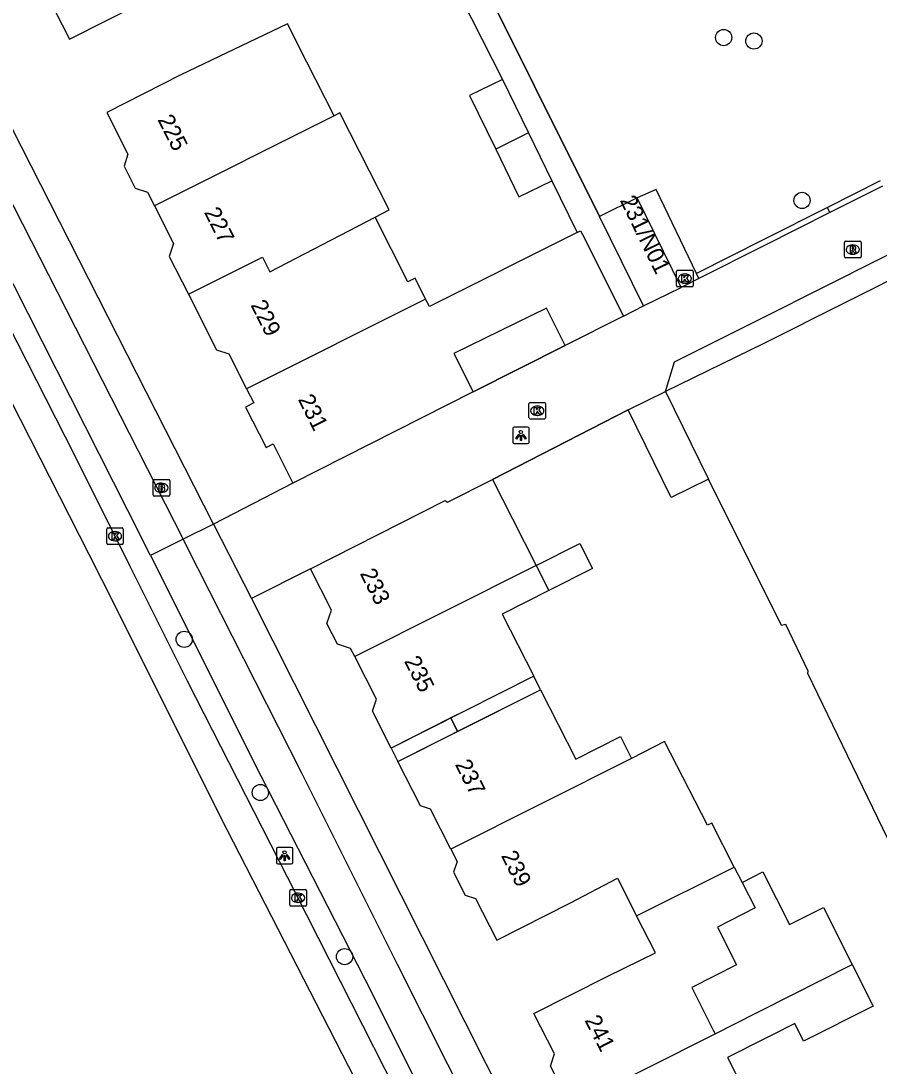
# Model space of a CAD drawing. Extents: x 162347 to 162868, y 381221 to 381813.
# Drawn here: x 162455.2 to 162507, y 381421.7 to 381484.8 of the extents above; entities that cross this region are included whole.
import ezdxf

# ---------------------------------------------------------------- set-up
doc = ezdxf.new("R2010")
doc.units = 0
for name, color, linetype in [('IMGEO_Boom', 7, 'Continuous'), ('IMGEO_Brandkraan', 7, 'Continuous'), ('IMGEO_Fietspad_open', 7, 'Continuous'), ('IMGEO_Groenvoorziening', 7, 'Continuous'), ('IMGEO_Hek', 7, 'Continuous'), ('IMGEO_Kolk', 7, 'Continuous'), ('IMGEO_Lichtpunt', 7, 'Continuous'), ('IMGEO_Muur', 7, 'Continuous'), ('IMGEO_Pand', 7, 'Continuous'), ('IMGEO_Pand_nummerreeks', 7, 'Continuous'), ('IMGEO_Pand_overbouw', 7, 'Continuous'), ('IMGEO_Parkeervlak_open', 7, 'Continuous'), ('IMGEO_Rijbaan_regionaal_gesloten', 7, 'Continuous'), ('IMGEO_Rioolput', 7, 'Continuous'), ('IMGEO_Voetpad_open', 7, 'Continuous')]:
    doc.layers.add(name, color=color, linetype=linetype)

msp = doc.modelspace()

# ---------------------------------------------------------------- linework, layer by layer
at = {"layer": 'IMGEO_Boom'}
for centre in [(162497.584, 381483.799), (162499.409, 381483.589), (162502.314, 381473.971), (162465.021, 381447.483), (162469.618, 381438.236), (162474.702, 381428.333)]:
    msp.add_circle(centre, 0.489, dxfattribs=at)
at = {"layer": 'IMGEO_Brandkraan'}
for p, q in [((162463.144, 381456.2), (162463.144, 381457.052)), ((162463.219, 381457.126), (162464.071, 381457.126)), ((162463.632, 381456.906), (162463.657, 381456.906)), ((162464.145, 381457.052), (162464.145, 381456.2)), ((162464.071, 381456.126), (162463.219, 381456.126)), ((162463.655, 381456.346), (162463.63, 381456.346))]:
    msp.add_line(p, q, dxfattribs=at)
for points in [[(162463.144, 381456.2), (162463.144, 381457.052)], [(162463.219, 381457.126), (162464.071, 381457.126)], [(162463.492, 381456.826), (162463.492, 381456.426), (162463.705, 381456.426)], [(162463.723, 381456.826), (162463.492, 381456.826)], [(162463.671, 381456.745), (162463.617, 381456.745), (162463.617, 381456.669)], [(162463.617, 381456.669), (162463.67, 381456.669)], [(162463.679, 381456.593), (162463.617, 381456.593), (162463.617, 381456.512)], [(162464.145, 381457.052), (162464.145, 381456.2)], [(162464.071, 381456.126), (162463.219, 381456.126)], [(162463.617, 381456.512), (162463.679, 381456.512)]]:
    msp.add_lwpolyline(points, dxfattribs=at)
for centre, radius, start, end in [((162463.221, 381457.05), 0.0765, 91.55205, 178.44795), ((162463.221, 381457.05), 0.0765, 91.55205, 178.44795), ((162463.672, 381456.707), 0.0379, 267.82845, 90.93552), ((162463.68, 381456.552), 0.0404, 269.87594, 90.50774), ((162463.727, 381456.681), 0.145, 59.4692, 91.53667), ((162463.752, 381456.728), 0.0922, 285.51372, 58.15012), ((162463.757, 381456.536), 0.105, 301.31148, 78.98903), ((162464.069, 381457.05), 0.0765, 1.55205, 88.44795), ((162464.069, 381457.05), 0.0765, 1.55205, 88.44795), ((162463.221, 381456.202), 0.0765, 181.55205, 268.44795), ((162463.221, 381456.202), 0.0765, 181.55205, 268.44795), ((162463.711, 381456.677), 0.251, 268.66757, 293.53466), ((162464.069, 381456.202), 0.0765, 271.55205, 358.44795), ((162464.069, 381456.202), 0.0765, 271.55205, 358.44795)]:
    msp.add_arc(centre, radius, start, end, dxfattribs=at)
for centre, major_axis, ratio, start_param, end_param in [((162463.631, 381456.626), (-0.387, 0.002), 0.722429, 4.712389, 7.853982), ((162463.656, 381456.626), (-0.39, 0.002), 0.717154, 1.570796, 4.712389)]:
    msp.add_ellipse(centre, major_axis=major_axis, ratio=ratio, start_param=start_param, end_param=end_param, dxfattribs=at)
at = {"layer": 'IMGEO_Fietspad_open'}
for points in [[(162362.948, 381654.184), (162366.42, 381647.346), (162373.547, 381633.19), (162382.229, 381616.136), (162390.519, 381599.747), (162395.607, 381589.625), (162403.109, 381574.937), (162411.637, 381558.14), (162419.849, 381541.928), (162427.81, 381526.456), (162437.491, 381507.399), (162441.265, 381500), (162456.812, 381469.521), (162464.953, 381453.521)], [(162462.98, 381452.545), (162461.625, 381455.252), (162453.003, 381472.242), (162452.042, 381474.115), (162448.969, 381480.106), (162445.183, 381487.485), (162438.839, 381500), (162438.556, 381500.561), (162435.485, 381506.617), (162424.679, 381527.923), (162421.176, 381534.828)], [(162464.953, 381453.521), (162462.98, 381452.545)], [(162464.953, 381453.521), (162465.14, 381453.154), (162472.078, 381439.472), (162477.869, 381427.872), (162483.955, 381415.809), (162489.755, 381404.169), (162492.348, 381399.133), (162497.104, 381389.763), (162499.049, 381385.783), (162500, 381383.793), (162500.427, 381382.899)], [(162462.98, 381452.545), (162469.637, 381439.248), (162476.371, 381426.111), (162479.042, 381420.737), (162481.428, 381415.937), (162487.993, 381402.969), (162489.759, 381399.475), (162492.407, 381394.237), (162495.213, 381388.634), (162496.259, 381386.553), (162497.483, 381384.161), (162498.087, 381382.794), (162500, 381378.338), (162501.86, 381374.016), (162502.544, 381372.608), (162503.198, 381371.132), (162503.882, 381369.785), (162504.669, 381367.657), (162505.515, 381365.488), (162506.466, 381362.909), (162506.901, 381361.574)]]:
    msp.add_lwpolyline(points, dxfattribs=at)
at = {"layer": 'IMGEO_Groenvoorziening'}
for points in [[(162560.659, 381495.777), (162538.071, 381484.442), (162500, 381465.338), (162494.068, 381462.441)], [(162507.027, 381475.147), (162503.84, 381473.541)], [(162503.84, 381473.541), (162500, 381471.606), (162495.941, 381469.56)], [(162503.991, 381473.241), (162503.84, 381473.541)], [(162512.923, 381424.22), (162502.662, 381445.418), (162502.674, 381445.558), (162501.325, 381448.372), (162501.075, 381448.315), (162496.664, 381457.154)]]:
    msp.add_lwpolyline(points, dxfattribs=at)
at = {"layer": 'IMGEO_Hek'}
msp.add_lwpolyline([(162474.241, 381507.266), (162474.364, 381504.517), (162490.097, 381473.002)], dxfattribs=at)
at = {"layer": 'IMGEO_Kolk'}
for p, q in [((162494.739, 381468.827), (162494.739, 381469.679)), ((162494.814, 381469.753), (162495.666, 381469.753)), ((162495.227, 381469.533), (162495.252, 381469.533)), ((162495.74, 381469.679), (162495.74, 381468.827)), ((162495.666, 381468.753), (162494.814, 381468.753)), ((162495.25, 381468.973), (162495.225, 381468.973)), ((162485.832, 381460.853), (162485.832, 381461.705)), ((162485.907, 381461.779), (162486.759, 381461.779)), ((162486.833, 381461.705), (162486.833, 381460.853)), ((162486.343, 381460.999), (162486.318, 381460.999)), ((162486.32, 381461.559), (162486.345, 381461.559)), ((162486.759, 381460.779), (162485.907, 381460.779)), ((162460.342, 381453.28), (162460.342, 381454.132)), ((162460.417, 381454.206), (162461.269, 381454.206)), ((162461.343, 381454.132), (162461.343, 381453.28)), ((162460.83, 381453.986), (162460.855, 381453.986)), ((162461.269, 381453.206), (162460.417, 381453.206)), ((162460.853, 381453.426), (162460.828, 381453.426)), ((162471.394, 381431.456), (162471.394, 381432.308)), ((162471.469, 381432.382), (162472.321, 381432.382)), ((162471.882, 381432.162), (162471.907, 381432.162)), ((162472.395, 381432.308), (162472.395, 381431.456)), ((162472.321, 381431.382), (162471.469, 381431.382)), ((162471.905, 381431.602), (162471.88, 381431.602))]:
    msp.add_line(p, q, dxfattribs=at)
for points in [[(162494.739, 381468.827), (162494.739, 381469.679)], [(162494.814, 381469.753), (162495.666, 381469.753)], [(162495.06, 381469.453), (162495.183, 381469.453), (162495.183, 381469.302), (162495.313, 381469.453), (162495.477, 381469.453), (162495.331, 381469.302), (162495.484, 381469.053), (162495.332, 381469.053), (162495.247, 381469.217), (162495.183, 381469.15), (162495.183, 381469.053), (162495.06, 381469.053), (162495.06, 381469.453)], [(162495.74, 381469.679), (162495.74, 381468.827)], [(162495.666, 381468.753), (162494.814, 381468.753)], [(162485.832, 381460.853), (162485.832, 381461.705)], [(162485.907, 381461.779), (162486.759, 381461.779)], [(162486.833, 381461.705), (162486.833, 381460.853)], [(162486.153, 381461.479), (162486.276, 381461.479), (162486.276, 381461.328), (162486.406, 381461.479), (162486.57, 381461.479), (162486.424, 381461.328), (162486.577, 381461.079), (162486.425, 381461.079), (162486.34, 381461.243), (162486.276, 381461.176), (162486.276, 381461.079), (162486.153, 381461.079), (162486.153, 381461.479)], [(162486.759, 381460.779), (162485.907, 381460.779)], [(162460.342, 381453.28), (162460.342, 381454.132)], [(162460.417, 381454.206), (162461.269, 381454.206)], [(162461.343, 381454.132), (162461.343, 381453.28)], [(162460.663, 381453.906), (162460.786, 381453.906), (162460.786, 381453.755), (162460.916, 381453.906), (162461.08, 381453.906), (162460.934, 381453.755), (162461.087, 381453.506), (162460.935, 381453.506), (162460.85, 381453.67), (162460.786, 381453.603), (162460.786, 381453.506), (162460.663, 381453.506), (162460.663, 381453.906)], [(162461.269, 381453.206), (162460.417, 381453.206)], [(162471.394, 381431.456), (162471.394, 381432.308)], [(162471.469, 381432.382), (162472.321, 381432.382)], [(162471.715, 381432.082), (162471.838, 381432.082), (162471.838, 381431.931), (162471.968, 381432.082), (162472.132, 381432.082), (162471.986, 381431.931), (162472.139, 381431.682), (162471.987, 381431.682), (162471.902, 381431.846), (162471.838, 381431.779), (162471.838, 381431.682), (162471.715, 381431.682), (162471.715, 381432.082)], [(162472.395, 381432.308), (162472.395, 381431.456)], [(162472.321, 381431.382), (162471.469, 381431.382)]]:
    msp.add_lwpolyline(points, dxfattribs=at)
for centre, start, end in [((162494.816, 381469.677), 91.55205, 178.44795), ((162494.816, 381469.677), 91.55205, 178.44795), ((162495.664, 381469.677), 1.55205, 88.44795), ((162495.664, 381469.677), 1.55205, 88.44795), ((162494.816, 381468.829), 181.55205, 268.44795), ((162494.816, 381468.829), 181.55205, 268.44795), ((162495.664, 381468.829), 271.55205, 358.44795), ((162495.664, 381468.829), 271.55205, 358.44795), ((162485.909, 381461.703), 91.55205, 178.44795), ((162485.909, 381461.703), 91.55205, 178.44795), ((162486.757, 381461.703), 1.55205, 88.44795), ((162486.757, 381461.703), 1.55205, 88.44795), ((162485.909, 381460.855), 181.55205, 268.44795), ((162485.909, 381460.855), 181.55205, 268.44795), ((162486.757, 381460.855), 271.55205, 358.44795), ((162486.757, 381460.855), 271.55205, 358.44795), ((162460.419, 381454.13), 91.55205, 178.44795), ((162460.419, 381454.13), 91.55205, 178.44795), ((162461.267, 381454.13), 1.55205, 88.44795), ((162461.267, 381454.13), 1.55205, 88.44795), ((162460.419, 381453.282), 181.55205, 268.44795), ((162460.419, 381453.282), 181.55205, 268.44795), ((162461.267, 381453.282), 271.55205, 358.44795), ((162461.267, 381453.282), 271.55205, 358.44795), ((162471.471, 381432.306), 91.55205, 178.44795), ((162471.471, 381432.306), 91.55205, 178.44795), ((162472.319, 381432.306), 1.55205, 88.44795), ((162472.319, 381432.306), 1.55205, 88.44795), ((162471.471, 381431.458), 181.55205, 268.44795), ((162471.471, 381431.458), 181.55205, 268.44795), ((162472.319, 381431.458), 271.55205, 358.44795), ((162472.319, 381431.458), 271.55205, 358.44795)]:
    msp.add_arc(centre, 0.0765, start, end, dxfattribs=at)
for centre, major_axis, ratio, start_param, end_param in [((162495.226, 381469.253), (-0.387, 0.002), 0.722429, 4.712389, 7.853982), ((162495.251, 381469.253), (-0.39, 0.002), 0.717154, 1.570796, 4.712389), ((162486.319, 381461.279), (-0.387, 0.002), 0.722429, 4.712389, 7.853982), ((162486.344, 381461.279), (-0.39, 0.002), 0.717154, 1.570796, 4.712389), ((162460.829, 381453.706), (-0.387, 0.002), 0.722429, 4.712389, 7.853982), ((162460.854, 381453.706), (-0.39, 0.002), 0.717154, 1.570796, 4.712389), ((162471.881, 381431.882), (-0.387, 0.002), 0.722429, 4.712389, 7.853982), ((162471.906, 381431.882), (-0.39, 0.002), 0.717154, 1.570796, 4.712389)]:
    msp.add_ellipse(centre, major_axis=major_axis, ratio=ratio, start_param=start_param, end_param=end_param, dxfattribs=at)
at = {"layer": 'IMGEO_Lichtpunt'}
for p, q in [((162484.847, 381460.197), (162484.847, 381459.39)), ((162484.847, 381460.197), (162484.847, 381459.39)), ((162485.749, 381460.292), (162484.941, 381460.292)), ((162485.749, 381460.292), (162484.941, 381460.292)), ((162485.843, 381459.39), (162485.843, 381460.197)), ((162485.843, 381459.39), (162485.843, 381460.197)), ((162484.941, 381459.296), (162485.749, 381459.296)), ((162484.941, 381459.296), (162485.749, 381459.296)), ((162470.582, 381434.829), (162470.582, 381434.022)), ((162470.582, 381434.829), (162470.582, 381434.022)), ((162471.484, 381434.924), (162470.676, 381434.924)), ((162471.484, 381434.924), (162470.676, 381434.924)), ((162471.578, 381434.022), (162471.578, 381434.829)), ((162471.578, 381434.022), (162471.578, 381434.829)), ((162470.676, 381433.928), (162471.484, 381433.928)), ((162470.676, 381433.928), (162471.484, 381433.928))]:
    msp.add_line(p, q, dxfattribs=at)
for points in [[(162485.221, 381459.861), (162485.26, 381459.833), (162485.072, 381459.571), (162485.034, 381459.598), (162485.221, 381459.861)], [(162485.323, 381459.813), (162485.37, 381459.813), (162485.37, 381459.491), (162485.323, 381459.491), (162485.323, 381459.813)], [(162485.433, 381459.833), (162485.471, 381459.86), (162485.658, 381459.598), (162485.619, 381459.57), (162485.433, 381459.833)], [(162470.956, 381434.493), (162470.995, 381434.465), (162470.807, 381434.203), (162470.769, 381434.23), (162470.956, 381434.493)], [(162471.058, 381434.445), (162471.105, 381434.445), (162471.105, 381434.123), (162471.058, 381434.123), (162471.058, 381434.445)], [(162471.168, 381434.465), (162471.206, 381434.492), (162471.393, 381434.23), (162471.354, 381434.202), (162471.168, 381434.465)]]:
    msp.add_lwpolyline(points, dxfattribs=at)
for centre in [(162485.346, 381459.995), (162471.081, 381434.627)]:
    msp.add_circle(centre, 0.0994, dxfattribs=at)
for centre, start, end in [((162484.941, 381460.197), 90, 180), ((162484.941, 381460.197), 90, 180), ((162485.749, 381460.197), 0, 90), ((162485.749, 381460.197), 0, 90), ((162484.941, 381459.39), 180, 270), ((162484.941, 381459.39), 180, 270), ((162485.749, 381459.39), 270, 0), ((162485.749, 381459.39), 270, 360), ((162470.676, 381434.829), 90, 180), ((162470.676, 381434.829), 90, 180), ((162471.484, 381434.829), 0, 90), ((162471.484, 381434.829), 0, 90), ((162470.676, 381434.022), 180, 270), ((162470.676, 381434.022), 180, 270), ((162471.484, 381434.022), 270, 0), ((162471.484, 381434.022), 270, 360)]:
    msp.add_arc(centre, 0.0946, start, end, dxfattribs=at)
at = {"layer": 'IMGEO_Muur'}
for points in [[(162482.458, 381462.415), (162488.025, 381465.214)], [(162483.626, 381457.134), (162491.815, 381461.335)]]:
    msp.add_lwpolyline(points, dxfattribs=at)
at = {"layer": 'IMGEO_Pand'}
for points in [[(162455.242, 381489.376), (162455.676, 381488.518), (162455.426, 381487.753), (162456.046, 381486.527), (162456.789, 381486.284), (162458.093, 381483.707), (162462.554, 381485.966), (162466.136, 381487.779), (162466.036, 381487.977), (162468.845, 381489.399), (162467.607, 381491.843), (162466.077, 381494.864)], [(162474.066, 381479.08), (162472.431, 381482.309), (162471.258, 381484.626), (162464.815, 381481.546), (162460.354, 381479.287), (162461.627, 381476.772), (162461.387, 381476.041), (162462.063, 381474.706), (162462.809, 381474.462), (162463.225, 381473.639)], [(162484.24, 381481.274), (162482.244, 381480.303), (162483.822, 381477.059)], [(162484.24, 381481.274), (162485.806, 381478.056)], [(162474.066, 381479.08), (162463.225, 381473.639)], [(162476.538, 381472.961), (162477.393, 381473.394), (162474.423, 381479.261), (162474.066, 381479.08)], [(162485.806, 381478.056), (162483.822, 381477.059)], [(162485.806, 381478.056), (162487.218, 381475.153)], [(162483.822, 381477.059), (162485.222, 381474.182), (162487.218, 381475.153)], [(162463.225, 381473.639), (162464.375, 381471.367), (162464.119, 381470.585), (162465.272, 381468.307)], [(162492.37, 381474.118), (162490.097, 381473.002)], [(162495.02, 381468.72), (162492.37, 381474.118)], [(162492.747, 381467.604), (162490.097, 381473.002)], [(162465.272, 381468.307), (162469.74, 381470.549), (162470.19, 381469.657), (162476.538, 381472.961)], [(162479.591, 381468.015), (162478.952, 381469.277), (162478.516, 381469.056), (162476.538, 381472.961)], [(162488.733, 381472.039), (162479.821, 381467.56), (162479.591, 381468.015)], [(162488.733, 381472.039), (162488.94, 381472.143), (162489.057, 381471.911), (162491.536, 381466.979)], [(162492.747, 381467.604), (162495.02, 381468.72)], [(162465.272, 381468.307), (162466.973, 381464.949), (162467.715, 381464.705), (162468.785, 381462.592)], [(162479.591, 381468.015), (162468.785, 381462.592)], [(162488.025, 381465.214), (162486.889, 381467.475), (162481.288, 381464.726), (162482.458, 381462.415)], [(162491.536, 381466.979), (162488.025, 381465.214)], [(162468.785, 381462.592), (162469.214, 381461.745), (162468.728, 381461.499), (162469.959, 381459.066), (162470.385, 381459.282), (162471.586, 381456.911)], [(162482.458, 381462.415), (162471.586, 381456.911)], [(162491.815, 381461.335), (162494.068, 381462.441)], [(162494.068, 381462.441), (162496.664, 381457.154)], [(162496.664, 381457.154), (162494.411, 381456.048), (162491.815, 381461.335)], [(162472.642, 381451.739), (162480.771, 381455.855), (162480.915, 381455.761), (162483.626, 381457.134)], [(162483.626, 381457.134), (162484.835, 381454.745), (162486.257, 381451.935)], [(162486.257, 381451.935), (162488.907, 381453.263), (162489.667, 381451.747), (162487.023, 381450.422)], [(162475.313, 381446.45), (162475.068, 381446.933), (162474.268, 381447.195), (162473.637, 381448.441), (162473.902, 381449.25), (162472.642, 381451.739)], [(162486.257, 381451.935), (162475.313, 381446.45)], [(162486.257, 381451.935), (162487.023, 381450.422)], [(162487.023, 381450.422), (162484.222, 381449.004), (162486.116, 381445.261), (162481.973, 381443.172), (162477.508, 381440.921), (162476.386, 381443.138), (162476.623, 381443.862), (162475.313, 381446.45)], [(162481.115, 381434.818), (162479.896, 381437.224), (162479.278, 381437.427), (162477.921, 381440.106), (162482.389, 381442.352), (162486.535, 381444.436), (162488.651, 381440.256), (162491.346, 381441.62), (162492.028, 381440.288)], [(162498.218, 381433.738), (162496.86, 381436.388), (162496.605, 381436.257), (162494.017, 381441.307), (162492.028, 381440.288)], [(162492.028, 381440.288), (162481.115, 381434.818)], [(162481.115, 381434.818), (162481.489, 381434.079), (162481.276, 381433.431), (162481.977, 381432.048), (162482.601, 381431.843), (162483.881, 381429.316), (162488.342, 381431.575), (162491.168, 381433.077), (162492.321, 381430.8)], [(162492.321, 381430.8), (162498.218, 381433.738)], [(162498.218, 381433.738), (162498.693, 381432.81)], [(162498.693, 381432.81), (162499.955, 381433.446), (162501.554, 381430.273), (162503.602, 381431.305), (162505.342, 381427.853)], [(162498.693, 381432.81), (162499.482, 381431.27), (162497.208, 381430.105), (162498.36, 381427.831), (162495.653, 381426.46), (162496.957, 381423.886), (162497.062, 381423.68)], [(162488.866, 381419.549), (162488.573, 381420.128), (162487.812, 381420.377), (162487.129, 381421.726), (162487.368, 381422.456), (162486.134, 381424.894), (162490.595, 381427.152), (162493.458, 381428.555), (162492.321, 381430.8)], [(162497.062, 381423.68), (162499.56, 381424.939), (162499.805, 381425.062), (162505.342, 381427.853)], [(162505.342, 381427.853), (162506.606, 381425.343), (162502.409, 381423.228), (162501.873, 381424.292), (162500.536, 381423.616), (162500, 381423.345), (162497.811, 381422.237), (162500, 381417.91), (162500.238, 381417.439)], [(162488.866, 381419.549), (162497.062, 381423.68)]]:
    msp.add_lwpolyline(points, dxfattribs=at)
at = {"layer": 'IMGEO_Pand_overbouw'}
for points in [[(162481.106, 381442.735), (162481.519, 381441.915), (162486.535, 381444.436), (162486.116, 381445.261), (162481.973, 381443.172)], [(162477.508, 381440.921), (162477.921, 381440.106), (162481.519, 381441.915), (162481.106, 381442.735)]]:
    msp.add_lwpolyline(points, close=True, dxfattribs=at)
at = {"layer": 'IMGEO_Parkeervlak_open'}
msp.add_lwpolyline([(162491.213, 381393.798), (162488.593, 381398.901), (162482.572, 381410.845), (162477.842, 381420.165), (162475.125, 381425.517), (162471.76, 381432.148), (162465.212, 381444.966), (162461.732, 381451.927), (162458.433, 381458.526), (162450.881, 381473.37), (162447.777, 381479.473), (162444.379, 381486.155), (162439.222, 381496.36), (162437.342, 381500), (162436.324, 381501.971), (162434.333, 381505.984), (162432.557, 381509.562), (162427.946, 381518.514), (162423.461, 381527.291), (162422.698, 381528.784), (162420.29, 381533.582), (162419.988, 381534.171)], dxfattribs=at)
at = {"layer": 'IMGEO_Rijbaan_regionaal_gesloten'}
msp.add_lwpolyline([(162489.821, 381392.102), (162487.907, 381395.912), (162482.094, 381407.301), (162475.708, 381420.227), (162467.623, 381435.981), (162460.044, 381451.092), (162459.288, 381452.598), (162452.163, 381466.562), (162442.935, 381484.761), (162435.196, 381500), (162427.322, 381515.351), (162426.042, 381517.985), (162418.813, 381534.719), (162419.506, 381535.112)], dxfattribs=at)
at = {"layer": 'IMGEO_Rioolput'}
for p, q in [((162504.873, 381470.578), (162504.873, 381471.43)), ((162504.948, 381471.504), (162505.8, 381471.504)), ((162505.361, 381471.284), (162505.386, 381471.284)), ((162505.874, 381471.43), (162505.874, 381470.578)), ((162505.8, 381470.504), (162504.948, 381470.504)), ((162505.384, 381470.724), (162505.359, 381470.724))]:
    msp.add_line(p, q, dxfattribs=at)
for points in [[(162504.873, 381470.578), (162504.873, 381471.43)], [(162504.948, 381471.504), (162505.8, 381471.504)], [(162505.462, 381471.202), (162505.21, 381471.204), (162505.21, 381470.804)], [(162505.388, 381471.123), (162505.334, 381471.123), (162505.334, 381471.042)], [(162505.874, 381471.43), (162505.874, 381470.578)], [(162505.8, 381470.504), (162504.948, 381470.504)], [(162505.21, 381470.804), (162505.334, 381470.804), (162505.334, 381470.966), (162505.345, 381470.966)], [(162505.334, 381471.042), (162505.386, 381471.042)], [(162505.392, 381470.937), (162505.463, 381470.804), (162505.603, 381470.804), (162505.538, 381470.93)]]:
    msp.add_lwpolyline(points, dxfattribs=at)
for centre, radius, start, end in [((162504.95, 381471.428), 0.0765, 91.55205, 178.44795), ((162504.95, 381471.428), 0.0765, 91.55205, 178.44795), ((162505.394, 381471.027), 0.0964, 77.00612, 93.18647), ((162505.408, 381471.084), 0.0378, 276.66336, 79.67722), ((162505.461, 381471.092), 0.109, 350.36119, 89.41601), ((162505.798, 381471.428), 0.0765, 1.55205, 88.44795), ((162505.798, 381471.428), 0.0765, 1.55205, 88.44795), ((162504.95, 381470.58), 0.0765, 181.55205, 268.44795), ((162504.95, 381470.58), 0.0765, 181.55205, 268.44795), ((162505.344, 381470.913), 0.0533, 26.02933, 88.69889), ((162505.37, 381471.231), 0.19, 274.7715, 282.96867), ((162505.459, 381471.092), 0.112, 277.58423, 350.98172), ((162505.443, 381470.877), 0.108, 29.51342, 73.79051), ((162505.798, 381470.58), 0.0765, 271.55205, 358.44795), ((162505.798, 381470.58), 0.0765, 271.55205, 358.44795)]:
    msp.add_arc(centre, radius, start, end, dxfattribs=at)
for centre, major_axis, ratio, start_param, end_param in [((162505.36, 381471.004), (-0.387, 0.002), 0.722429, 4.712389, 7.853982), ((162505.385, 381471.004), (-0.39, 0.002), 0.717154, 1.570796, 4.712389)]:
    msp.add_ellipse(centre, major_axis=major_axis, ratio=ratio, start_param=start_param, end_param=end_param, dxfattribs=at)
at = {"layer": 'IMGEO_Voetpad_open'}
for points in [[(162466.79, 381454.429), (162443.597, 381500), (162364.764, 381654.894)], [(162490.097, 381473.002), (162474.364, 381504.517), (162474.241, 381507.266), (162478.842, 381509.219)], [(162494.068, 381462.441), (162494.61, 381464.221), (162500, 381466.932), (162559.862, 381497.036)], [(162479.051, 381491.515), (162479.248, 381491.116), (162484.24, 381481.274)], [(162487.218, 381475.153), (162488.733, 381472.039)], [(162495.941, 381469.56), (162493.498, 381474.638), (162492.37, 381474.118)], [(162507.173, 381474.837), (162503.991, 381473.241)], [(162503.991, 381473.241), (162500, 381471.234), (162496.084, 381469.265)], [(162496.084, 381469.265), (162495.02, 381468.72)], [(162496.084, 381469.265), (162495.941, 381469.56)], [(162491.536, 381466.979), (162492.747, 381467.604)], [(162488.025, 381465.214), (162482.458, 381462.415)], [(162491.815, 381461.335), (162483.626, 381457.134)], [(162471.586, 381456.911), (162466.79, 381454.429)], [(162466.79, 381454.429), (162464.953, 381453.521)], [(162466.79, 381454.429), (162469.085, 381449.938)], [(162472.642, 381451.739), (162469.085, 381449.938)], [(162469.085, 381449.938), (162500, 381388.592), (162507.249, 381374.207), (162509.669, 381369.232)]]:
    msp.add_lwpolyline(points, dxfattribs=at)

# ---------------------------------------------------------------- texts
at = {"layer": 'IMGEO_Pand_nummerreeks'}
for s, rotation, p in [('225', 296.65511, (162463.392, 381478.852)), ('231/N01', 295.94905, (162491.299, 381473.984)), ('227', 296.65379, (162466.2, 381473.258)), ('229', 296.65379, (162469.008, 381467.664)), ('231', 296.65379, (162471.867, 381461.969)), ('233', 296.79052, (162475.605, 381451.46)), ('235', 296.85536, (162478.276, 381446.175)), ('237', 296.86305, (162481.348, 381439.933)), ('239', 296.69389, (162484.13, 381434.431)), ('241', 297.07777, (162489.168, 381424.495))]:
    msp.add_text(s, height=1, rotation=rotation, dxfattribs=at).set_placement(p)

doc.saveas('drawing.dxf')
